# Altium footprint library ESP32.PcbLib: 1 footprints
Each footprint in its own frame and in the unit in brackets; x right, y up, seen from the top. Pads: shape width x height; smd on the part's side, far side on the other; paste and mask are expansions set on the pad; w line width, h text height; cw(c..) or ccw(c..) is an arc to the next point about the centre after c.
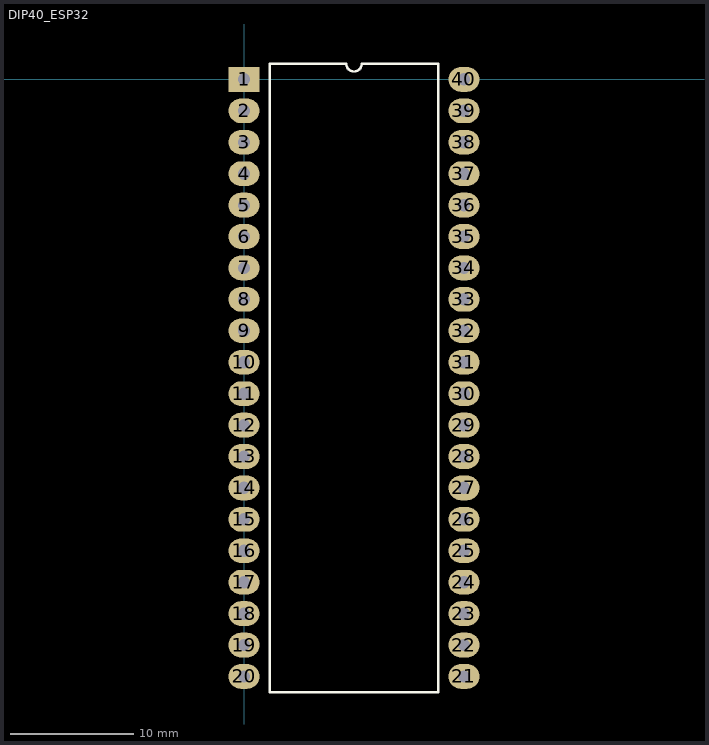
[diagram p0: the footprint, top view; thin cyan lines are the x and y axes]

## DIP40_ESP32 [mm]
height 0.127
pads (40):
  rect 2.5x2 hole 1: 1(0,0)
  oval 2.5x2 hole 1: 2(0,-2.54) 3(0,-5.08) 4(0,-7.62) 5(0,-10.16) 6(0,-12.7) 7(0,-15.24) 8(0,-17.78) 9(0,-20.32) 10(0,-22.86) 11(0,-25.4) 12(0,-27.94) 13(0,-30.48) 14(0,-33.02) 15(0,-35.56) 16(0,-38.1) 17(0,-40.64) 18(0,-43.18) 19(0,-45.72) 20(0,-48.26) 21(17.78,-48.26) 22(17.78,-45.72) 23(17.78,-43.18) 24(17.78,-40.64) 25(17.78,-38.1) 26(17.78,-35.56) 27(17.78,-33.02) 28(17.78,-30.48) 29(17.78,-27.94) 30(17.78,-25.4) 31(17.78,-22.86) 32(17.78,-20.32) 33(17.78,-17.78) 34(17.78,-15.24) 35(17.78,-12.7) 36(17.78,-10.16) 37(17.78,-7.62) 38(17.78,-5.08) 39(17.78,-2.54) 40(17.78,0)
Top Overlay:
  lines w0.2: 2.085,-49.53 2.085,1.27 8.255,1.27 ccw(c8.89,1.27) 9.525,1.27 15.695,1.27 15.695,-49.53 2.085,-49.53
